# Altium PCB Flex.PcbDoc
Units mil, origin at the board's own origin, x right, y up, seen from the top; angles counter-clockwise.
Board outline 5010 x 3500 mil, 6 copper layers (Top Layer, GND, Mid1, Mid2, PWR, Bottom Layer), stack 32.112 mil thick; 22 components, 29 nets, 175 pads, 0 vias.
Unrouted connection lines stored in the file: 35.
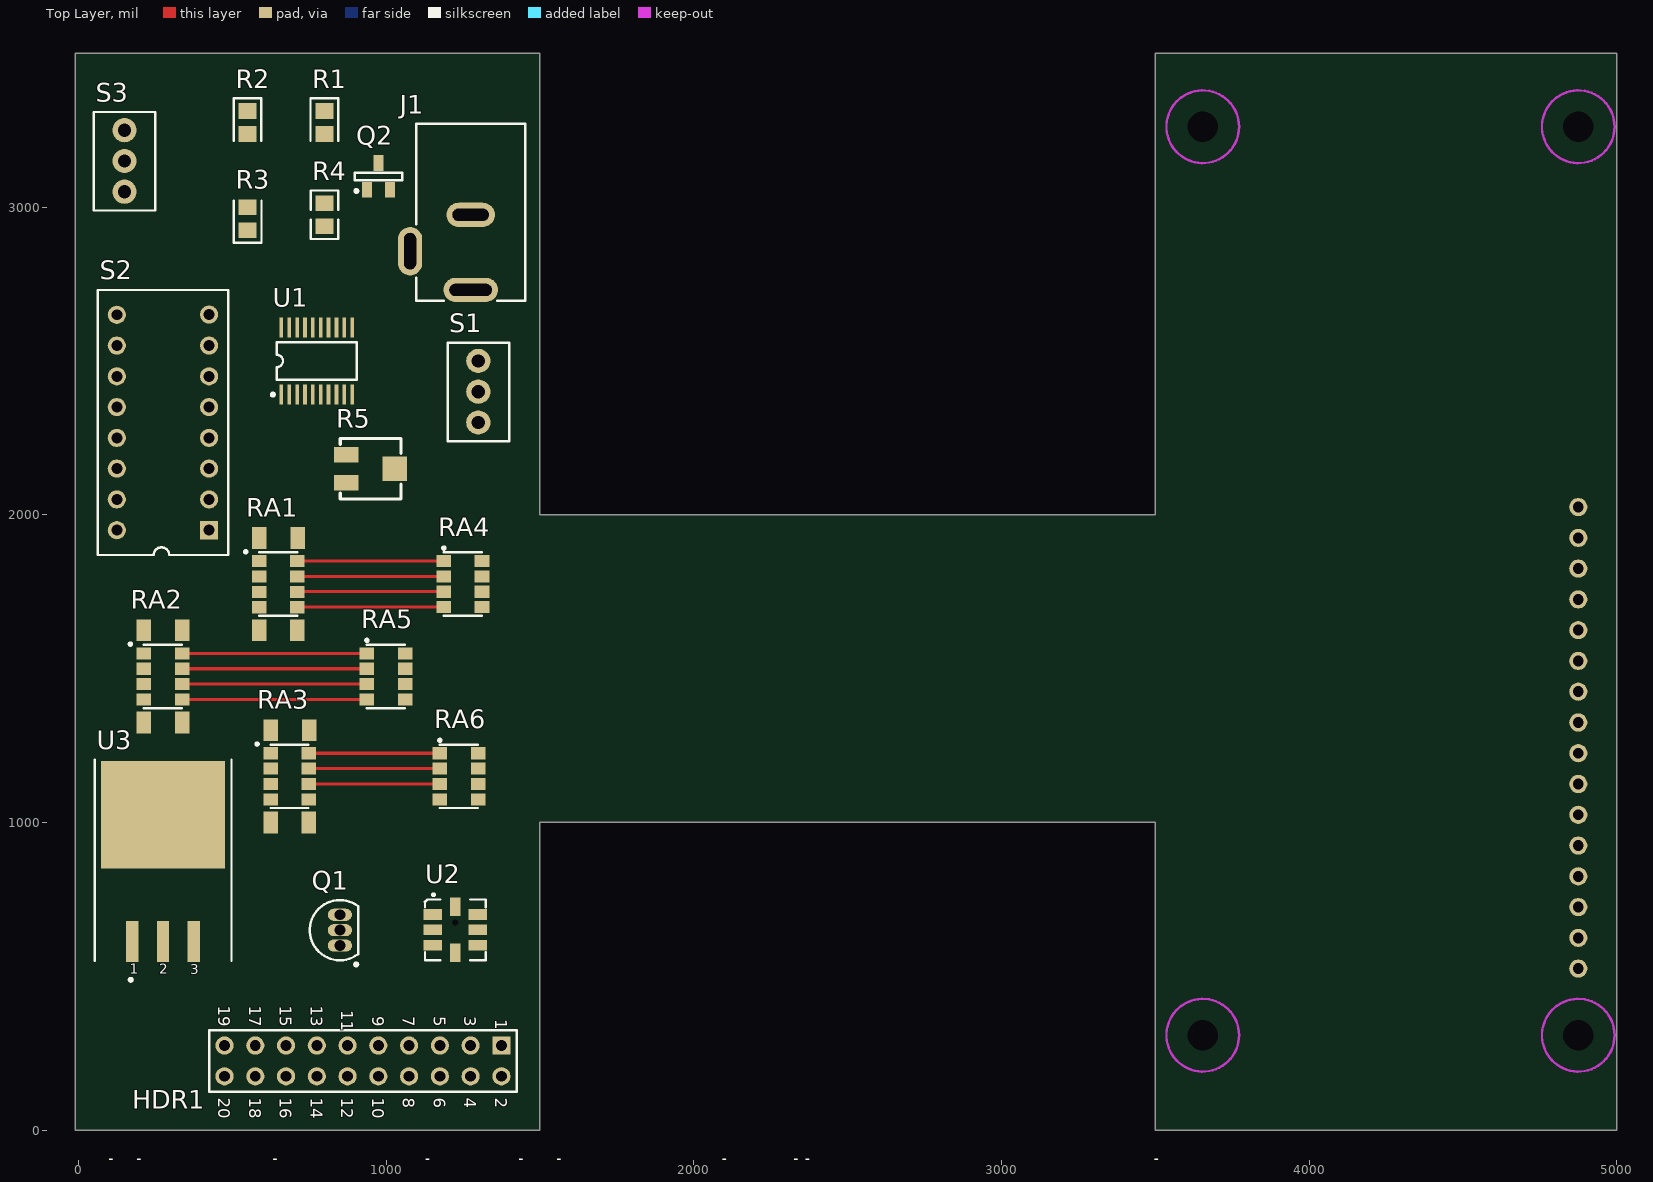
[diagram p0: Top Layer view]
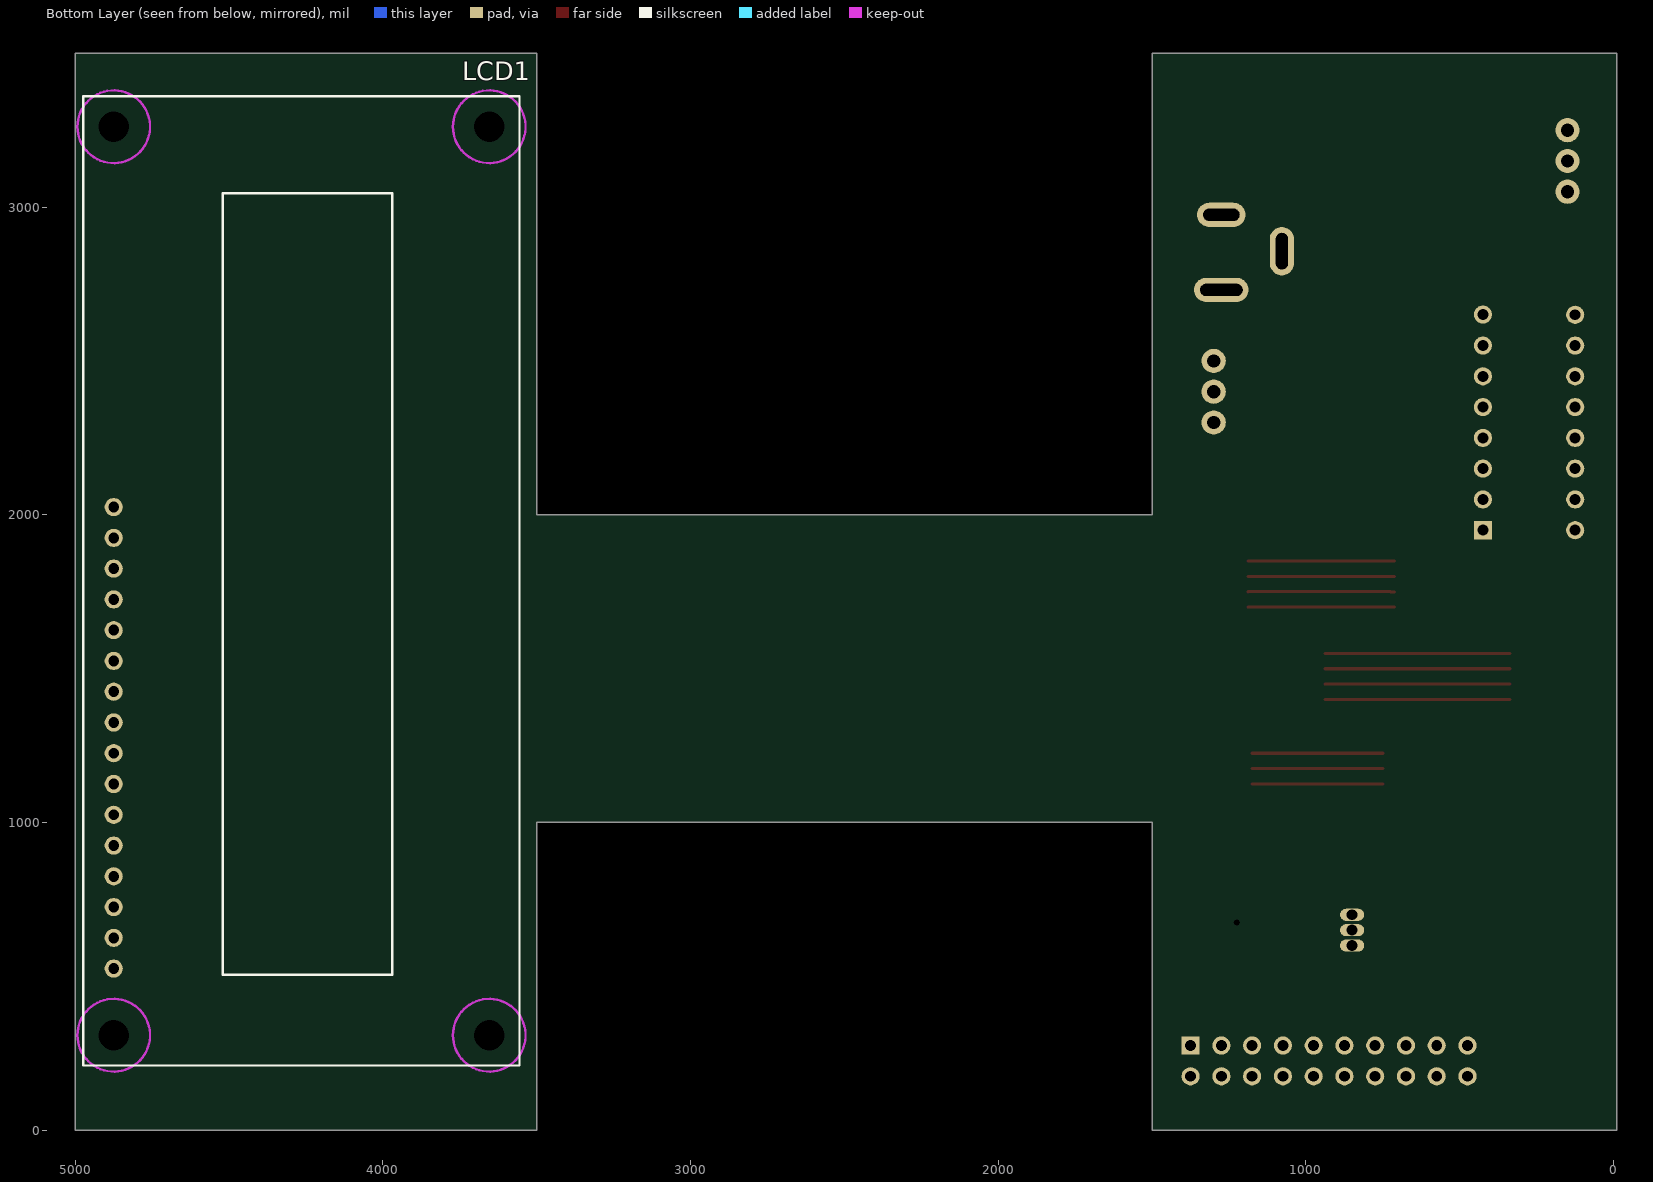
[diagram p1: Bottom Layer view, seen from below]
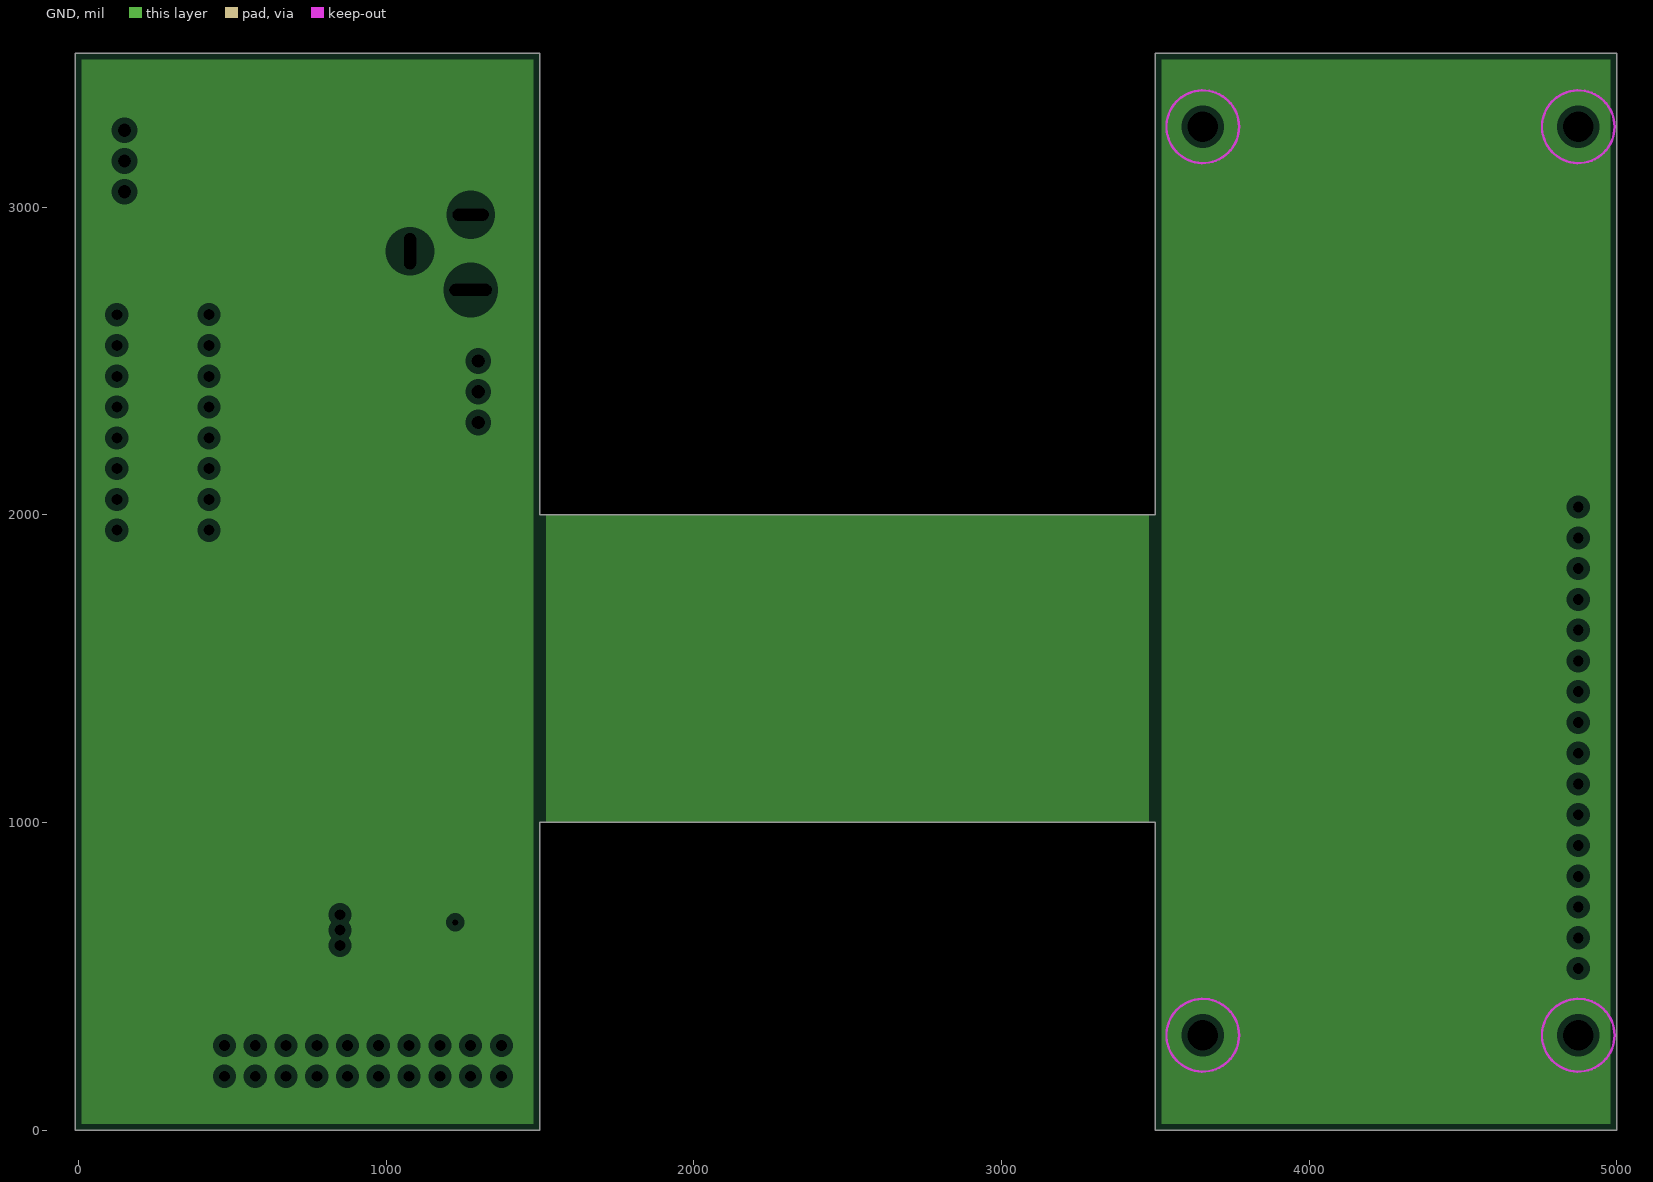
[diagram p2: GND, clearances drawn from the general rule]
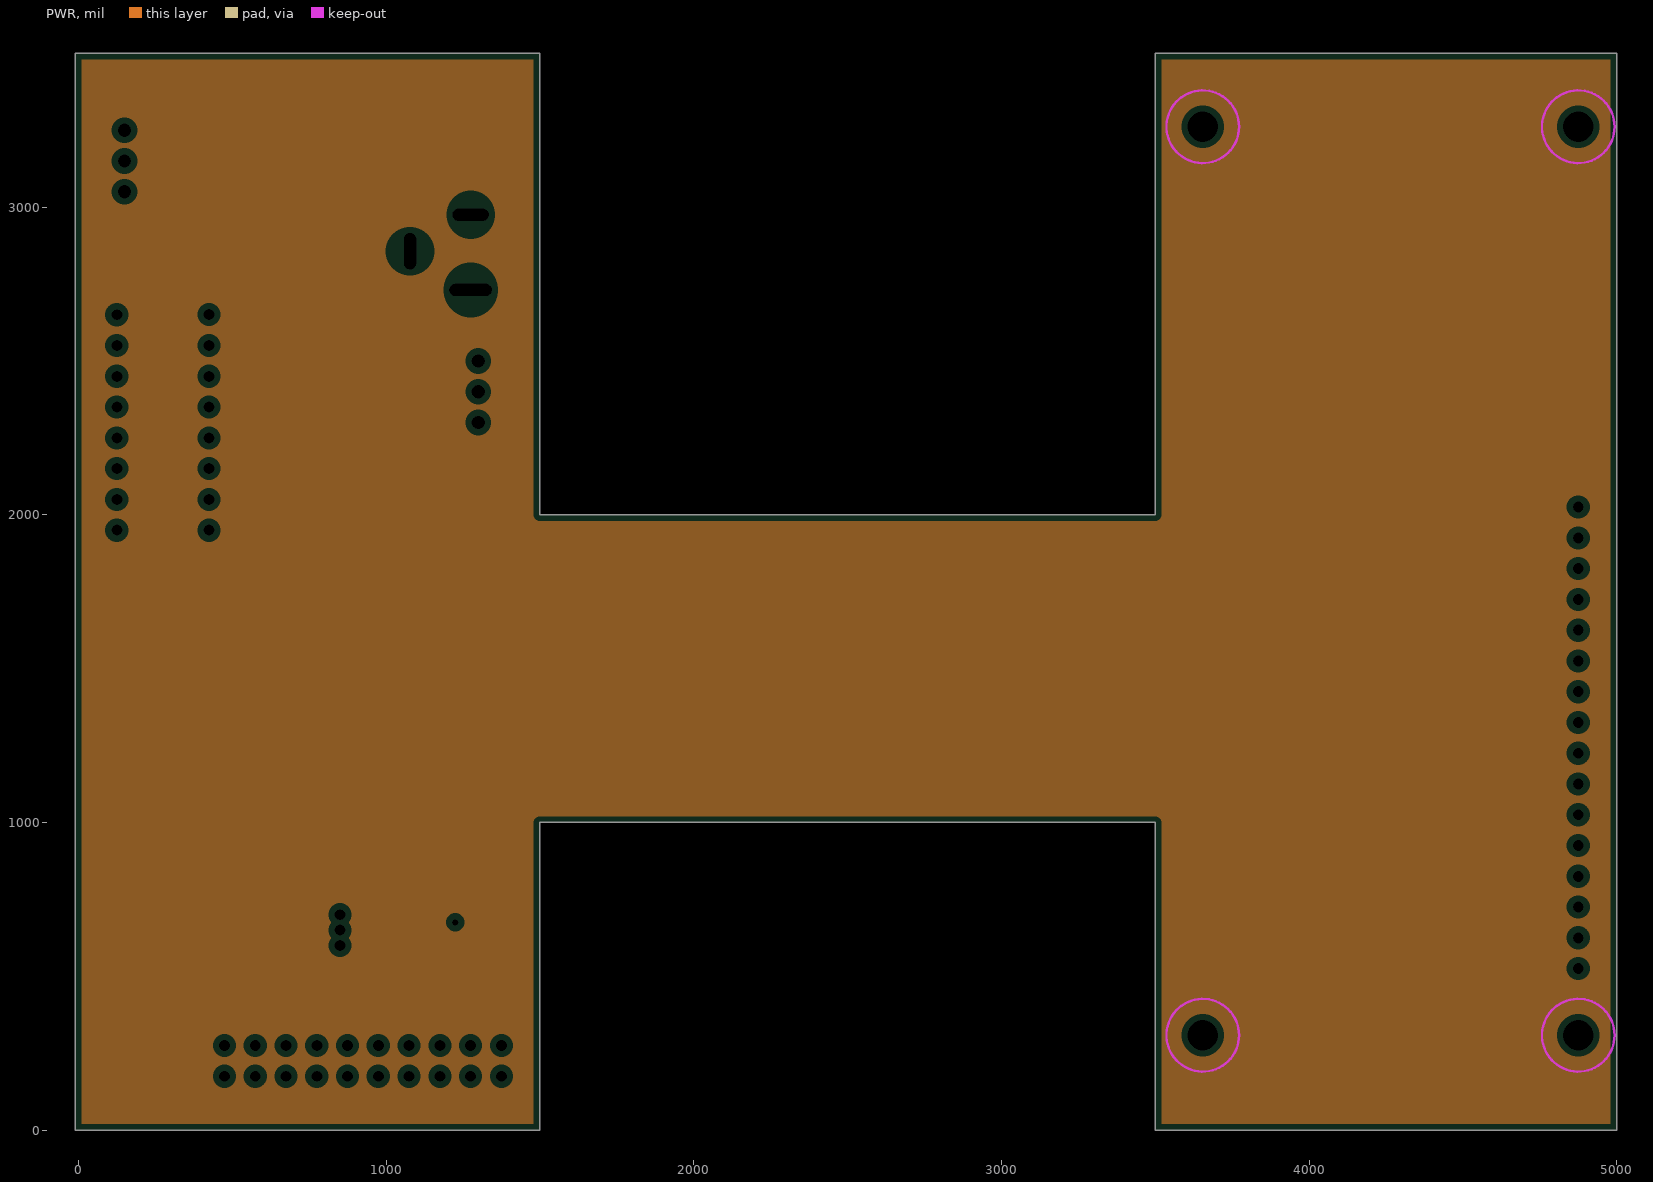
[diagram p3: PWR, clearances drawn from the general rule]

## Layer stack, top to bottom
Top Solder: solder mask 0.4724, FC-001, Dk 4
Top Solder: solder mask 0.4, Solder Resist, Dk 3.5
Top Layer: signal copper 1.4
Dielectric 4: prepreg 2.8, PP-006, Dk 4.1
GND: plane copper 1.378
Dielectric 2: prepreg 2.8, PP-006, Dk 4.1
Mid1: signal copper 1.378
Dielectric 1: dielectric 12.6, FR-4, Dk 4.8
Mid2: signal copper 1.378
Dielectric 3: prepreg 2.8, PP-006, Dk 4.1
PWR: plane copper 1.378
Dielectric 5: prepreg 2.8, PP-006, Dk 4.1
Bottom Layer: signal copper 1.4
Flex Bottom Coverlay: solder mask 0.4, Solder Resist, Dk 3.5
Flex Bottom Coverlay: solder mask 0.4724, FC-001, Dk 4

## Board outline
3500,0 5000,0 5000,3500 3500,3500 3500,2000 1500,2000 1500,3500 -10,3500 -10,0 1500,0 1500,1000 3500,1000
board region "Rigid Layer Stack Region - Left.": -10,0 1500,0 1500,3500 -10,3500
board region "Rigid Layer Stack Region - Right": 3500,0 5000,0 5000,3500 3500,3500
board region FLEX: 1500,1000 3500,1000 3500,2000 1500,2000

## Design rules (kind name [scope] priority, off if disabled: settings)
BoardOutlineClearance [All] p1: gap=10 ignorepadtopadclearanceinfootprint=FALSE except(0: Arc-SplitContinuation Track-SplitContinuation SMDPad-SplitContinuation THPad-SplitContinuation Via-SplitContinuation Fill-SplitContinuation Poly-SplitContinuation Region-SplitContinuation Text-SplitContinuation)
Clearance [All] p1: gap=10 ignorepadtopadclearanceinfootprint=FALSE except(0: Arc-Hole Track-Hole SMDPad-Hole THPad-Hole Via-Hole Fill-Hole Poly-Hole Region-Hole Text-Hole)
DiffPairsRouting [All] p1: maxlimit=10 minlimit=10 mostfreqgap=10 toplayer_minwidth=15 toplayer_maxwidth=15 toplayer_prefwidth=15 midlayer1_minwidth=15 midlayer1_maxwidth=15 midlayer1_prefwidth=15 midlayer2_minwidth=15 midlayer2_maxwidth=15 midlayer2_prefwidth=15 bottomlayer_minwidth=15 bottomlayer_maxwidth=15 bottomlayer_prefwidth=15 substack1={B5968FE7-CA1D-4CA5-8B2D-EEA0998704F7} toplayer_{b5968fe7-ca1d-4ca5-8b2d-eea0998704f7}_minwidth=15 toplayer_{b5968fe7-ca1d-4ca5-8b2d-eea0998704f7}_maxwidth=15 toplayer_{b5968fe7-ca1d-4ca5-8b2d-eea0998704f7}_prefwidth=15 midlayer1_{b5968fe7-ca1d-4ca5-8b2d-eea0998704f7}_minwidth=15 midlayer1_{b5968fe7-ca1d-4ca5-8b2d-eea0998704f7}_maxwidth=15 midlayer1_{b5968fe7-ca1d-4ca5-8b2d-eea0998704f7}_prefwidth=15 midlayer2_{b5968fe7-ca1d-4ca5-8b2d-eea0998704f7}_minwidth=15 midlayer2_{b5968fe7-ca1d-4ca5-8b2d-eea0998704f7}_maxwidth=15 midlayer2_{b5968fe7-ca1d-4ca5-8b2d-eea0998704f7}_prefwidth=15 bottomlayer_{b5968fe7-ca1d-4ca5-8b2d-eea0998704f7}_minwidth=15 bottomlayer_{b5968fe7-ca1d-4ca5-8b2d-eea0998704f7}_maxwidth=15 bottomlayer_{b5968fe7-ca1d-4ca5-8b2d-eea0998704f7}_prefwidth=15 maxuncoupledlength=500
PlaneClearance [All] p1: clearance=20
PlaneConnect [All] p1: planeconnectstyle=Relief reliefexpansion=20 reliefentries=4 reliefconductorwidth=10 reliefairgap=10
PolygonConnect [All] p1: connectstyle=Relief reliefconductorwidth=10 reliefentries=4 polygonreliefangle="90 Angle" airgapwidth=10
RoutingVias [All] p1: holewidth=28 width=50 viastyle="Through Hole" minholewidth=28 minwidth=50 maxholewidth=28 maxwidth=50
SolderMaskExpansion [All] p1: expansion=4 istentingtop=FALSE
Width [All] p1: maxlimit=10 minlimit=10 preferedwidth=10 substack1={B5968FE7-CA1D-4CA5-8B2D-EEA0998704F7}
27 further rules are at their usual default settings.

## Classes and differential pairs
net class LCD_DB[7..0]: LCD_DB0 LCD_DB1 LCD_DB2 LCD_DB3 LCD_DB4 LCD_DB5 LCD_DB6 LCD_DB7

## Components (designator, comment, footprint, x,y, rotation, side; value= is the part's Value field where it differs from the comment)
HDR1 "Header 10X2" HDR2X10 1374.56,275.28 r180 top
J1 "KLD-0202-B" KLD-0202 1275.04,3269.96 r270 top
LCD1 "162A" 162A 4875,525 r90 bottom
Q1 "2N3904" TO-92A 850,650 r0 top
Q2 "2N7002" SO-G3 975,3100 r0 top
R1 "68R" CC2012-0805 800,3275 r270 top
R2 "68R" CC2012-0805 550,3275 r270 top
R3 "560R" CC2012-0805 549.72,2962.19 r90 top
R4 "10K" CR2012-0805 800,2975 r90 top
R5 "20K" POT4MM-2 950,2150 r0 top
RA1 "4K7" MNR34T 650,1775 r180 top
RA2 "4K7" MNR34T 275,1475 r180 top
RA3 "4K7" MNR34T 687.01,1150.35 r180 top
RA4 "270R" MNR34 1250,1775 r0 top
RA5 "270R" MNR34 1000,1475 r0 top
RA6 "270R" MNR34 1237.12,1150.28 r0 top
S1 "TL36WW050" PCB_SWITCH 1300.2,2299.55 r90 top
S2 "A6ER-8104" DIP-16-KEY 425.06,1950.44 r90 top
S3 "TL36WW050" PCB_SWITCH 150.2,3049.55 r90 top
U1 "XCF02SVO20C" VO20 775,2500 r0 top
U2 "ADXL202E" E-8 1225.02,651.02 r0 top
U3 "LM1084IS-ADJ" TO-263 175.22,613.24 r0 top

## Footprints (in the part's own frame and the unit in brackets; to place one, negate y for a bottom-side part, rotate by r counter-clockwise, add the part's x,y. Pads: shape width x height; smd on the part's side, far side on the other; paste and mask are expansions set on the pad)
162A [mm]
  round 1.5 hole 0.9: 1(0,0) 2(2.54,0) 3(5.08,0) 4(7.62,0) 5(10.16,0) 6(12.7,0) 7(15.24,0) 8(17.78,0) 9(20.32,0) 10(22.86,0) 11(25.4,0) 12(27.94,0) 13(30.48,0) 14(33.02,0) 15(35.56,0) 16(38.1,0)
  round 2.3 hole 2.5 unplated: M1(-5.5,0) M2(69.5,0) M3(-5.5,-31) M4(69.5,-31)
  Keep-Out Layer circle w0.2: c69.5,0 r3
  Keep-Out Layer circle w0.2: c69.5,-31 r3
  Keep-Out Layer circle w0.2: c-5.5,-31 r3
  Keep-Out Layer circle w0.2: c-5.5,0 r3
  silkscreen extent -8,-33.5 72,2.5, body extent -8.01,-33.5 72,2.5, height 10.16
CC2012-0805 [mm]
  rect 1.3x1.5 smd: 1(-0.945,-0.007) 2(0.955,-0.007)
  silkscreen extent -1.99,-1.16 1.51,1.14, body extent -1.52,-0.7 1.52,0.7, height 0.76
CR2012-0805 [mm]
  rect 1.3x1.5 smd: 1(-0.946,0) 2(0.954,0)
  silkscreen extent -2,-1.15 2,1.15, body extent -1.52,-0.7 1.52,0.7, height 0.76
DIP-16-KEY [mm]
  rect 1.5x1.5 hole 0.9: 1(-0.011,0.001)
  round 1.5 hole 0.9: 2(2.529,0.001) 3(5.069,0.001) 4(7.609,0.001) 5(10.149,0.001) 6(12.689,0.001) 7(15.229,0.001) 8(17.789,0.001) 9(17.769,7.621) 10(15.229,7.621) 11(12.689,7.621) 12(10.149,7.621) 13(7.609,7.621) 14(5.069,7.621) 15(2.529,7.621) 16(-0.011,7.621)
  silkscreen extent -2.06,-1.59 19.82,9.2, body extent -2.03,-1.52 19.81,9.14, height 7.11
E-8 [mil]
  round 15 hole 20 unplated: 0(-0.02,23.98)
  rect 60x35 smd: 1(-72.85,49.98) 2(-72.85,-0.02) 3(-72.85,-50.02) 5(72.82,-50.02) 6(72.82,-0.02) 7(72.82,49.98)
  rect 35x60 smd: 4(-0.02,-74.82) 8(-0.02,74.79)
  silkscreen extent -98,-98 99,118, body extent -95,-95 95,95, height 80
HDR2X10 [mm]
  rect 1.5x1.5 hole 0.9: 1(-0.011,0.007)
  round 1.5 hole 0.9: 2(-0.011,2.547) 3(2.529,0.007) 4(2.529,2.547) 5(5.069,0.007) 6(5.069,2.547) 7(7.609,0.007) 8(7.609,2.547) 9(10.149,0.007) 10(10.149,2.547) 11(12.689,0.007) 12(12.689,2.547) 13(15.229,0.007) 14(15.229,2.547) 15(17.769,0.007) 16(17.769,2.547) 17(20.309,0.007) 18(20.309,2.547) 19(22.849,0.007) 20(22.849,2.547)
  silkscreen extent -1.28,-1.26 24.12,3.82, body extent -1.27,-1.27 24.13,3.81, height 10
KLD-0202 [mm]
  oval 2x4.5 hole 1 slot 3.5 at 90 deg: 1(13.692,-0.001)
  oval 2x4 hole 1 slot 3 at 90 deg: 2(7.492,-0.001)
  oval 4x2 hole 1 slot 3 at 0 deg: 3(10.492,-5.001)
  silkscreen extent -0.01,-4.5 14.59,4.5, body extent 0,-4.44 14.61,4.45, height 7.62
MNR34 [mm]
  rect 1.2x1 smd: 1(-1.578,1.898) 2(-1.578,0.628) 3(-1.578,-0.642) 4(-1.578,-1.912) 5(1.572,-1.912) 6(1.572,-0.642) 7(1.572,0.628) 8(1.572,1.898)
  silkscreen extent -1.68,-2.62 1.55,3.06, body extent -2.03,-2.29 2.03,2.29, height 1.27
MNR34T [mm]
  rect 1.2x1 smd: 1(1.575,-1.896) 2(1.575,-0.626) 3(1.575,0.644) 4(1.575,1.914) 5(-1.575,1.914) 6(-1.575,0.644) 7(-1.575,-0.626) 8(-1.575,-1.896)
  rect 1.2x1.8 smd: STP(-1.6,-3.801) STP(-1.575,3.819) STP(1.575,3.819) STP(1.575,-3.801)
  silkscreen extent -1.55,-2.76 2.79,2.62, body extent -1.65,-2.71 1.68,2.72, height 2
PCB_SWITCH [mm]
  round 2 hole 1.1: 1(0.011,0.005) 2(2.551,0.005) 3(5.091,0.005)
  silkscreen extent -1.54,-2.53 6.59,2.55, body extent -1.52,-2.54 6.6,2.54, height 15
POT4MM-2 [mm]
  rect 2x1.3 smd: CCW(-2.008,-1.162) CW(-2.008,1.138)
  rect 2x2 smd: W(1.992,-0.012)
  silkscreen extent -2.51,-2.51 2.49,2.49, body extent -2.92,-2.41 2.92,2.41, height 3.05
SO-G3 [mm]
  rect 0.85x1.3 smd: 1(-0.939,-1.107) 2(0.961,-1.107) 3(0.011,1.093)
  silkscreen extent -1.94,-1.33 1.96,0.29, body extent -1.65,-1.52 1.65,1.51, height 2.54
TO-92A [mm] "TO, Flat Index; 3 In-Line, Axial Leads; Body Dia. 4.5mm; Leads 0.51 x 0.48 mm (max)"
  oval 2x1 hole 0.9: 1(0,-1.27) 2(0,0) 3(0,1.27)
  silkscreen extent -2.48,-2.95 1.5,2.48, body extent -2.48,-2.5 1.5,2.5, height 6.86
TO-263 [mm]
  rect 1x3.4 smd: 1(-0.006,0.009) 2(2.534,0.009) 3(5.074,0.009)
  rect 10.25x8.9 smd: 4(2.534,10.459)
  silkscreen extent -3.11,-3.29 8.19,15.01, body extent -2.29,-1.14 7.37,14.35, height 2.03
VO20 [mm]
  rect 0.3x1.65 smd: 1(-2.929,-2.778) 2(-2.279,-2.778) 3(-1.629,-2.778) 4(-0.979,-2.778) 5(-0.329,-2.778) 6(0.321,-2.778) 7(0.971,-2.778) 8(1.621,-2.778) 9(2.271,-2.778) 10(2.921,-2.778) 11(2.921,2.772) 12(2.271,2.772) 13(1.621,2.772) 14(0.971,2.772) 15(0.321,2.772) 16(-0.329,2.772) 17(-0.979,2.772) 18(-1.629,2.772) 19(-2.279,2.772) 20(-2.929,2.772)
  silkscreen extent -3.75,-2.9 3.3,1.55, body extent -3.3,-3.56 3.3,3.55, height 1.52

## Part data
HDR1: "Header, 10-Pin, Dual row"
J1: "Low Voltage Power Supply Connector", Manufacturer=Kycon
LCD1: "16 char * 2 line LCD character display with b/light"
Q1: "NPN General Purpose Amplifier"
Q2: "N Channel Mosfet"
R1 R2: library part RES_2, "Resistor"
R3 R4: library part RES, "Resistor"
R5: library part "RPot SM", "Square Trimming Potentiometer"
RA1 RA2 RA3 RA4 RA5 RA6: library part MNR34, "3216x4 Resistor Array"
S1 S3: library part PCB_MOUNT_SWITCH, "SPDT Subminiature Toggle Switch"
S2: "DIP Switch Side actuator long liver Piano Key"
U1: "XCF00S Series, Platform Flash In-System Programmable Configuration 3.3V PROM, 20-Pin TSOP, 2-Megabit, Commercial Grade", PackageDocument="ver1.0, May-2003"
U2: "Accelerometer with Digital Output"
U3: "5A Low Dropout Possitive Regulators"

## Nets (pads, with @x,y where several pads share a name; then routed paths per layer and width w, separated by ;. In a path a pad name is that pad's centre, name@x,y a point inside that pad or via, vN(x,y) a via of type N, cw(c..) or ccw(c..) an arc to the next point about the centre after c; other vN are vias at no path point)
5V: LCD1.2 LCD1.15 R5.CW RA1.1 RA1.2 RA1.3 RA1.4 RA2.1 RA2.2 RA2.3 RA2.4 RA3.1 RA3.2 RA3.3 RA3.4
GND: LCD1.1 Q2.2 R4.1 R5.CCW
LCD_CONTRAST: LCD1.3 R5.W
LCD_DB0: RA5.5
LCD_DB1: RA5.6
LCD_DB2: RA5.7
LCD_DB3: RA5.8
LCD_DB4: RA4.5
LCD_DB5: RA4.6
LCD_DB6: RA4.7
LCD_DB7: RA4.8
LCD_DB#0: LCD1.7 RA2.5 RA5.4 | length 600.9
  Top Layer w10: RA2.5 937.81,1399.65 RA5.4
LCD_DB#1: LCD1.8 RA2.6 RA5.3 | length 600.9
  Top Layer w10: RA2.6 937.81,1449.65 RA5.3
LCD_DB#2: LCD1.9 RA2.7 RA5.2 | length 600.9
  Top Layer w10: RA2.7 937.81,1499.65 RA5.2
LCD_DB#3: LCD1.10 RA2.8 RA5.1 | length 600.9
  Top Layer w10: RA2.8 937.81,1549.65 RA5.1
LCD_DB#4: LCD1.11 RA1.5 RA4.4 | length 475.9
  Top Layer w10: RA1.5 1187.81,1699.65 RA4.4
LCD_DB#5: LCD1.12 RA1.6 RA4.3 | length 476.1
  Top Layer w10: RA1.6 724.65,1749.65 725,1750 1187.61,1750 RA4.3
LCD_DB#6: LCD1.13 RA1.7 RA4.2 | length 475.9
  Top Layer w10: RA1.7 1187.81,1799.65 RA4.2
LCD_DB#7: LCD1.14 RA1.8 RA4.1 | length 475.9
  Top Layer w10: RA1.8 1187.81,1849.65 RA4.1
LCD_E: RA6.8
LCD_E#: LCD1.6 RA3.8 RA6.1 | length 426
  Top Layer w10: RA3.8 RA6.1
LCD_LIGHT: R3.1
LCD_RS: RA6.6
LCD_RS#: LCD1.4 RA3.6 RA6.3 | length 426
  Top Layer w10: RA3.6 RA6.3
LCD_RW: RA6.7
LCD_RW#: LCD1.5 RA3.7 RA6.2 | length 426
  Top Layer w10: RA3.7 RA6.2
NetLCD1_16: LCD1.16 R1.1 R2.1
NetQ2_1: Q2.1 R3.2 R4.2
NetQ2_3: Q2.3 R1.2 R2.2
pads on no net: HDR1.1 HDR1.2 HDR1.3 HDR1.4 HDR1.5 HDR1.6 HDR1.7 HDR1.8 HDR1.9 HDR1.10 HDR1.11 HDR1.12 HDR1.13 HDR1.14 HDR1.15 HDR1.16 HDR1.17 HDR1.18 HDR1.19 HDR1.20 J1.1 J1.2 J1.3 LCD1.M1 LCD1.M2 LCD1.M3 LCD1.M4 Q1.1 Q1.2 Q1.3 RA1.STP RA2.STP RA3.5 RA3.STP RA6.4 RA6.5 S1.1 S1.2 S1.3 S2.1 S2.2 S2.3 S2.4 S2.5 S2.6 S2.7 S2.8 S2.9 S2.10 S2.11 S2.12 S2.13 S2.14 S2.15 S2.16 S3.1 S3.2 S3.3 U1.1 U1.2 U1.3 U1.4 U1.5 U1.6 U1.7 U1.8 U1.9 U1.10 U1.11 U1.12 U1.13 U1.14 U1.15 U1.16 U1.17 U1.18 U1.19 U1.20 U2.0 U2.1 U2.2 U2.3 U2.4 U2.5 U2.6 U2.7 U2.8 U3.1 U3.2 U3.3 U3.4

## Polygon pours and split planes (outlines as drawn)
no net on GND (split plane): 4979.9,3479.9 4979.9,20.1 3520.1,20.1 3520.1,3479.9
no net on GND (split plane): 1479.9,3479.9 1479.9,20.1 10.1,20.1 10.1,3479.9
no net on PWR (split plane): 1479.9,3479.9 1479.9,2000 1480.29,1996.08 1481.43,1992.31 1483.29,1988.84 1485.79,1985.79 1488.84,1983.29 1492.31,1981.43 1496.08,1980.29 1500,1979.9 3500,1979.9 3503.92,1980.29 3507.69,1981.43 3511.16,1983.29 3514.21,1985.79 3516.71,1988.84 3518.57,1992.31 3519.71,1996.08 3520.1,2000 3520.1,3479.9 4979.9,3479.9 4979.9,20.1 3520.1,20.1 3520.1,1000 3519.71,1003.92 3518.57,1007.69 3516.71,1011.16 3514.21,1014.21 3511.16,1016.71 3507.69,1018.57 3503.92,1019.71 3500,1020.1 1500,1020.1 1496.08,1019.71 1492.31,1018.57 1488.84,1016.71 1485.79,1014.21 1483.29,1011.16 1481.43,1007.69 1480.29,1003.92 1479.9,1000 1479.9,20.1 10.1,20.1 10.1,3479.9

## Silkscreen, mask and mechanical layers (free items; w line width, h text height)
Flex Top Overlay:
  text "Altium Advanced Training: '.Pcb_File_Name_No_Path'" at -5,-196.68 h100
Layer Stack:
  drawing of 621 lines, arcs and shapes, not listed
  text "Layer" at 6037.5,7069.36 h30
  text "Name" at 6242.46,7069.36 h30
  text "Material" at 6882.27,7069.36 h30
  text "Thickness" at 7312.16,7069.36 h30
  text "Constant" at 7637.07,7069.36 h30
  text "Gerber" at 7922,7069.36 h30
  text "Rigid 1" at 8156.95,7069.36 h30
  text "Flex" at 8411.89,7069.36 h30
  text "Top Overlay" at 6242.46,7009.36 h30
  text "GTO" at 7922,7009.36 h30
  text "Flex Top Overlay" at 6242.46,6949.36 h30
  text "GTO" at 7922,6949.36 h30
  text "Flex Top Coverlay" at 6242.46,6889.36 h30
  text "FC-001" at 6882.27,6889.36 h30
  text "0,47mil" at 7312.16,6889.36 h30
  text "4" at 7637.07,6889.36 h30
  text "GTS" at 7922,6889.36 h30
  text "Top Solder" at 6242.46,6829.36 h30
  text "Solder Resist" at 6882.27,6829.36 h30
  text "0,40mil" at 7312.16,6829.36 h30
  text "3.5" at 7637.07,6829.36 h30
  text "GTS" at 7922,6829.36 h30
  text "1" at 6037.5,6769.36 h30
  text "Top Layer" at 6242.46,6769.36 h30
  text "1,40mil" at 7312.16,6769.36 h30
  text "GTL" at 7922,6769.36 h30
  text "Dielectric 4" at 6242.46,6709.36 h30
  text "PP-006" at 6882.27,6709.36 h30
  text "2,80mil" at 7312.16,6709.36 h30
  text "4.1" at 7637.07,6709.36 h30
  text "2" at 6037.5,6649.36 h30
  text "GND" at 6242.46,6649.36 h30
  text "CF-004" at 6882.27,6649.36 h30
  text "1,38mil" at 7312.16,6649.36 h30
  text "GP1" at 7922,6649.36 h30
  text "Dielectric 2" at 6242.46,6589.36 h30
  text "PP-006" at 6882.27,6589.36 h30
  text "2,80mil" at 7312.16,6589.36 h30
  text "4.1" at 7637.07,6589.36 h30
  text "3" at 6037.5,6529.36 h30
  text "Mid1" at 6242.46,6529.36 h30
  text "CF-004" at 6882.27,6529.36 h30
  text "1,38mil" at 7312.16,6529.36 h30
  text "G1" at 7922,6529.36 h30
  text "Dielectric 1" at 6242.46,6469.36 h30
  text "FR-4" at 6882.27,6469.36 h30
  text "12,60mil" at 7312.16,6469.36 h30
  text "4.8" at 7637.07,6469.36 h30
  text "4" at 6037.5,6409.36 h30
  text "Mid2" at 6242.46,6409.36 h30
  text "CF-004" at 6882.27,6409.36 h30
  text "1,38mil" at 7312.16,6409.36 h30
  text "G2" at 7922,6409.36 h30
  text "Dielectric 3" at 6242.46,6349.36 h30
  text "PP-006" at 6882.27,6349.36 h30
  text "2,80mil" at 7312.16,6349.36 h30
  text "4.1" at 7637.07,6349.36 h30
  text "5" at 6037.5,6289.36 h30
  text "PWR" at 6242.46,6289.36 h30
  text "CF-004" at 6882.27,6289.36 h30
  text "1,38mil" at 7312.16,6289.36 h30
  text "GP2" at 7922,6289.36 h30
  text "Dielectric 5" at 6242.46,6229.36 h30
  text "PP-006" at 6882.27,6229.36 h30
  text "2,80mil" at 7312.16,6229.36 h30
  text "4.1" at 7637.07,6229.36 h30
  text "6" at 6037.5,6169.36 h30
  text "Bottom Layer" at 6242.46,6169.36 h30
  text "1,40mil" at 7312.16,6169.36 h30
  text "GBL" at 7922,6169.36 h30
  text "Bottom Solder" at 6242.46,6109.36 h30
  text "Solder Resist" at 6882.27,6109.36 h30
  text "0,40mil" at 7312.16,6109.36 h30
  text "3.5" at 7637.07,6109.36 h30
  text "GBS" at 7922,6109.36 h30
  text "Flex Bottom Coverlay" at 6242.46,6049.36 h30
  text "FC-001" at 6882.27,6049.36 h30
  text "0,47mil" at 7312.16,6049.36 h30
  text "4" at 7637.07,6049.36 h30
  text "GBS" at 7922,6049.36 h30
  text "Flex Bottom Overlay" at 6242.46,5989.36 h30
  text "GBO" at 7922,5989.36 h30
  text "Bottom Overlay" at 6242.46,5929.36 h30
  text "GBO" at 7922,5929.36 h30
  text "Total board thickness (Rigid 1):" at 6037.5,5869.36 h30
  text "32,91mil" at 7312.16,5869.36 h30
